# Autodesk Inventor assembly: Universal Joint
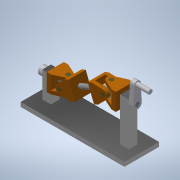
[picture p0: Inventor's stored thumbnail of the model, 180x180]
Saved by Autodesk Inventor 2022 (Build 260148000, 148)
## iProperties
Created: 2014-03
Part Number: Universal Joint
Document SubType Name: Assembly
Designer: John
Author: John
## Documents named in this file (8)
- C:\Users\helfenj\Desktop\Ex_Files_Autodesk_Inventor_2022_Essential_Training\Exercise Files\11_Adding parts to an assembly file\11_02\Universal Joint.iam
- C:\Users\helfenj\Desktop\Ex_Files_Autodesk_Inventor_2022_Essential_Training\Exercise Files\11_Adding parts to an assembly file\11_02\base.ipt
- C:\Users\helfenj\Desktop\Ex_Files_Autodesk_Inventor_2022_Essential_Training\Exercise Files\11_Adding parts to an assembly file\11_02\Connector.ipt
- C:\Users\helfenj\Desktop\Ex_Files_Autodesk_Inventor_2022_Essential_Training\Exercise Files\11_Adding parts to an assembly file\11_02\Joint.ipt
- C:\Users\helfenj\Desktop\Ex_Files_Autodesk_Inventor_2022_Essential_Training\Exercise Files\11_Adding parts to an assembly file\11_02\Connecting Rod.ipt
- C:\Users\helfenj\Desktop\Ex_Files_Autodesk_Inventor_2022_Essential_Training\Exercise Files\11_Adding parts to an assembly file\11_02\Crank Rod.ipt
- C:\Users\helfenj\Desktop\Ex_Files_Autodesk_Inventor_2022_Essential_Training\Exercise Files\11_Adding parts to an assembly file\11_02\Crank Handle.ipt
- C:\Users\helfenj\Desktop\Ex_Files_Autodesk_Inventor_2022_Essential_Training\Exercise Files\11_Adding parts to an assembly file\11_02\Pin.ipt
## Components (20 placed, 8 different names)
1. base:1 — Mate:1, Mate:2, Mate:9, Mate:10, Mate:15, Mate:16, Angle:3 - DRIVE THIS
2. Connector:1 — Mate:3, Mate:4, Mate:7, Mate:8
3. Connector:2 — Mate:5, Mate:6, Mate:11, Mate:12
4. Joint:1 — Mate:1, Mate:2, Mate:3, Mate:4, Flush:3, Angle:1, Insert:1, Insert:2
5. Joint:2 — Mate:5, Mate:6, Mate:9, Mate:10, Flush:4, Angle:2, Insert:5, Insert:8
6. Joint:3 — Mate:7, Mate:8, Mate:13, Flush:1, Mate:14, Insert:3, Insert:4
7. Joint:4 — Mate:11, Mate:12, Mate:13, Flush:1, Flush:2, Insert:6, Insert:7
8. Connecting Rod:1 — Mate:14, Flush:2
9. Crank Rod:1 — Mate:15, Flush:3, Flush:5, Mate:17
10. Crank Rod:2 — Flush:4, Mate:16, Flush:6, Mate:18
11. Crank Handle:1 - DRIVE — Flush:5, Mate:17, Angle:1, Angle:3 - DRIVE THIS
12. Crank Handle:2 — Flush:6, Angle:2, Mate:18
13. Pin:1 — Insert:1
14. Pin:2 — Insert:4
15. Pin:3 — Insert:3
16. Pin:4 — Insert:2
17. Pin:5 — Insert:7
18. Pin:6 — Insert:8
19. Pin:7 — Insert:6
20. Pin:8 — Insert:5
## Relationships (35: Mate 18, Insert 8, Flush 6, Angle 3)
- Mate:1: base:1 ↔ Joint:1
- Mate:2: base:1 ↔ Joint:1
- Mate:3: Connector:1 ↔ Joint:1
- Mate:4: Connector:1 ↔ Joint:1
- Mate:5: Connector:2 ↔ Joint:2
- Mate:6: Connector:2 ↔ Joint:2
- Mate:7: Connector:1 ↔ Joint:3
- Mate:8: Connector:1 ↔ Joint:3
- Mate:9: base:1 ↔ Joint:2
- Mate:10: base:1 ↔ Joint:2
- Mate:11: Connector:2 ↔ Joint:4
- Mate:12: Connector:2 ↔ Joint:4
- Mate:13: Joint:3 ↔ Joint:4
- Flush:1: Joint:3 ↔ Joint:4
- Mate:14: Joint:3 ↔ Connecting Rod:1
- Flush:2: Joint:4 ↔ Connecting Rod:1
- Mate:15: base:1 ↔ Crank Rod:1
- Flush:3: Joint:1 ↔ Crank Rod:1
- Flush:4: Joint:2 ↔ Crank Rod:2
- Mate:16: base:1 ↔ Crank Rod:2
- Flush:5: Crank Rod:1 ↔ Crank Handle:1 - DRIVE
- Mate:17: Crank Rod:1 ↔ Crank Handle:1 - DRIVE
- Angle:1: Joint:1 ↔ Crank Handle:1 - DRIVE
- Flush:6: Crank Rod:2 ↔ Crank Handle:2
- Angle:2: Joint:2 ↔ Crank Handle:2
- Mate:18: Crank Rod:2 ↔ Crank Handle:2
- Insert:1: Joint:1 ↔ Pin:1
- Insert:2: Joint:1 ↔ Pin:4
- Insert:3: Joint:3 ↔ Pin:3
- Insert:4: Joint:3 ↔ Pin:2
- Insert:5: Joint:2 ↔ Pin:8
- Insert:6: Joint:4 ↔ Pin:7
- Insert:7: Joint:4 ↔ Pin:5
- Insert:8: Joint:2 ↔ Pin:6
- Angle:3 - DRIVE THIS: base:1 ↔ Crank Handle:1 - DRIVE
